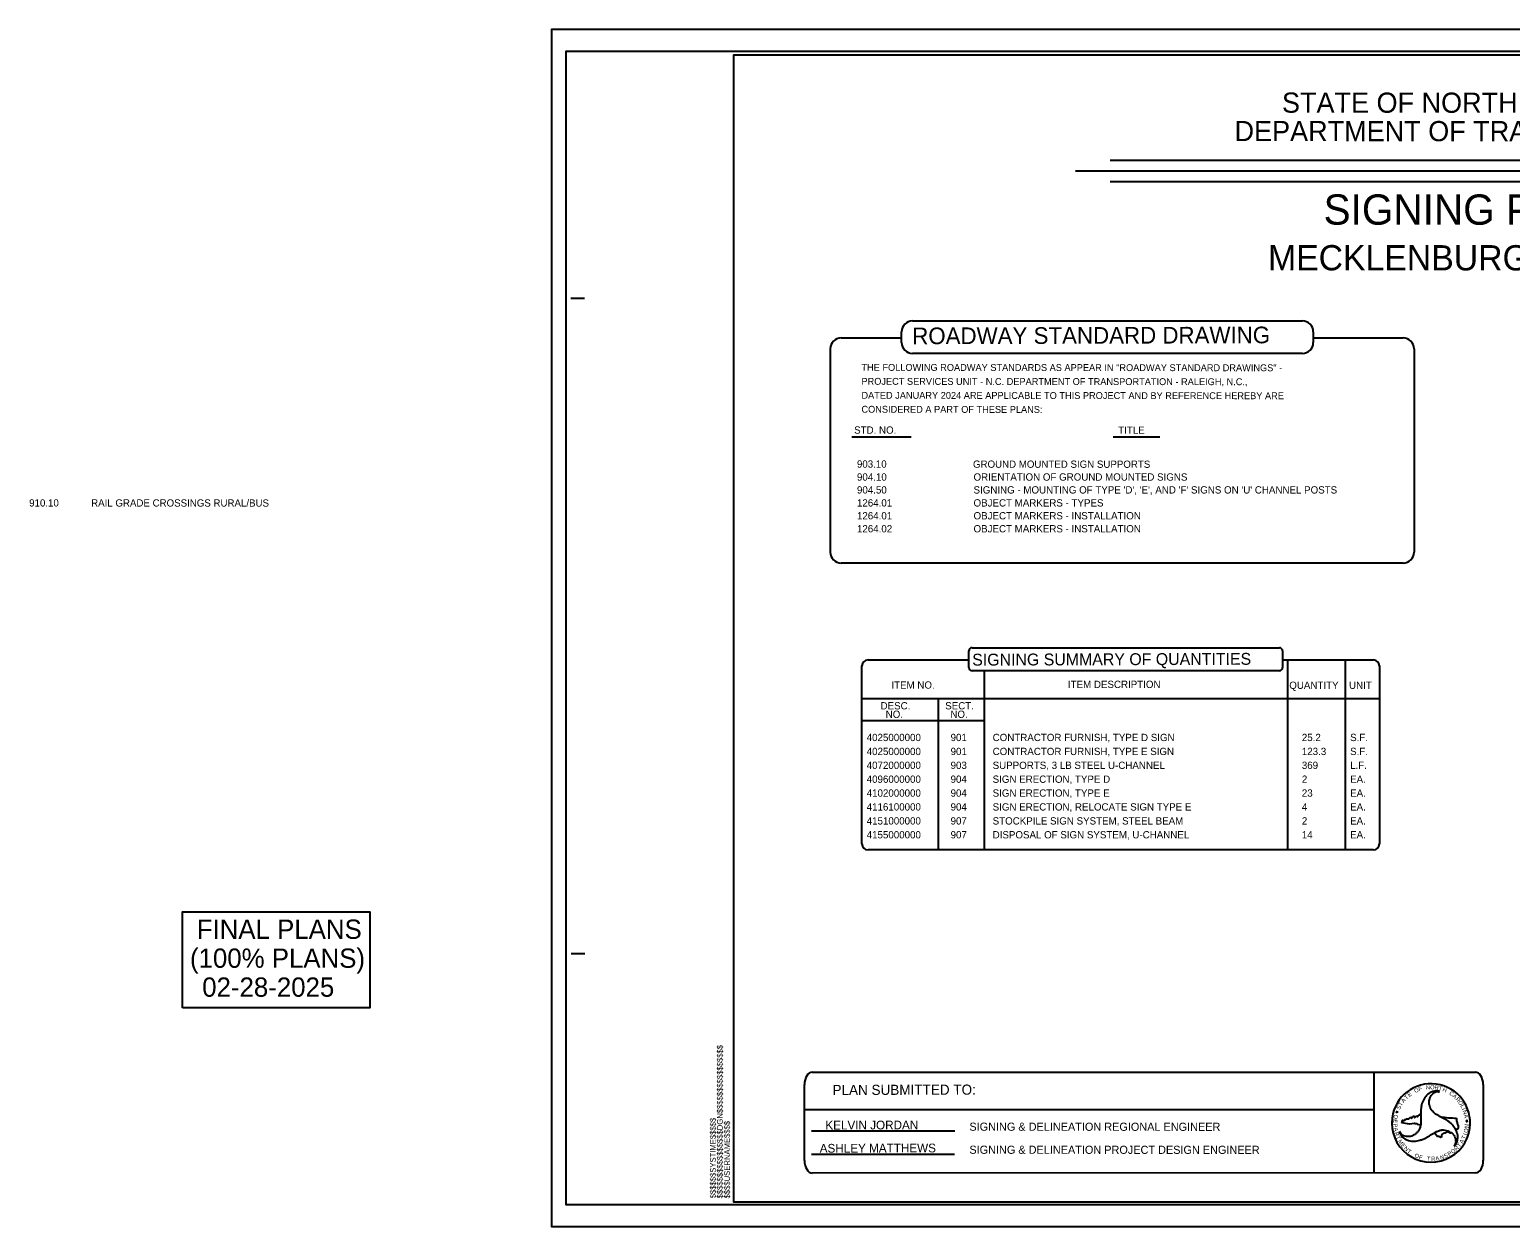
# Model space of a CAD drawing. Extents: x 2088591 to 2091186, y 751169 to 752405.
# Drawn here: x 2088591 to 2089946, y 751309 to 752405 of the extents above; entities that cross this region are included whole.
import ezdxf

# ---------------------------------------------------------------- set-up
doc = ezdxf.new("R2010")
doc.units = 0
for name, color, linetype in [('Default', 7, 'Continuous'), ('Sheet Block Title CELL', 7, 'Continuous'), ('Sheet Data Field CELL', 7, 'Continuous'), ('Sheet Plan CELL', 7, 'Continuous'), ('Sheet Sticker Incomplete CELL', 7, 'Continuous'), ('Sheet Sticker Preliminary CELL', 7, 'Continuous'), ('Sheet Title CELL', 7, 'Continuous'), ('Typical Detail Wedge1 CELL', 7, 'Continuous')]:
    doc.layers.add(name, color=color, linetype=linetype)

msp = doc.modelspace()

# ---------------------------------------------------------------- linework, layer by layer
at = {"layer": 'Default'}
for p, q in [((2089307.2, 751450), (2089914.1, 751450.1)), ((2089821.1, 751450.1), (2089821.1, 751357.8)), ((2089300, 751369.2), (2089300, 751438.6)), ((2089921.3, 751438.6), (2089921.4, 751369.3)), ((2089300, 751415.7), (2089821.1, 751415.9)), ((2089306.4, 751396.3), (2089437.6, 751396.2)), ((2089306.4, 751375.1), (2089437.5, 751375)), ((2089914.2, 751357.8), (2089307.2, 751357.7))]:
    msp.add_line(p, q, dxfattribs=at)
for centre, major_axis, start_param, end_param in [((2089307.2, 751438.6), (0, 11.5), 0.000702, 1.571498), ((2089914.1, 751438.6), (0, 11.5), 4.713091, 6.283887), ((2089307.2, 751369.2), (0, -11.5), 4.713091, 6.283887), ((2089914.2, 751369.3), (0, -11.5), 0.000702, 1.571498)]:
    msp.add_ellipse(centre, major_axis=major_axis, ratio=0.62659, start_param=start_param, end_param=end_param, dxfattribs=at)
at = {"layer": 'Sheet Block Title CELL'}
msp.add_lwpolyline([(2090751.5, 752404.7), (2089068.6, 752404.7), (2089068.6, 751308.8), (2090751.5, 751308.8)], close=True, dxfattribs=at)
at = {"layer": 'Sheet Plan CELL'}
for p, q in [((2089081.6, 751328.8), (2089081.6, 751328.8)), ((2089068.6, 751308.8), (2089068.6, 751308.8))]:
    msp.add_line(p, q, dxfattribs=at)
at = {"layer": 'Sheet Sticker Incomplete CELL'}
msp.add_lwpolyline([(2090735.1, 752381.4), (2089235.1, 752381.4), (2089235.1, 751331.4), (2090735.1, 751331.4)], close=True, dxfattribs=at)
at = {"layer": 'Sheet Sticker Preliminary CELL'}
msp.add_lwpolyline([(2088730.8, 751508.9), (2088730.8, 751597), (2088902.2, 751597), (2088902.2, 751508.9)], close=True, dxfattribs=at)
at = {"layer": 'Sheet Title CELL'}
for p, q in [((2089580, 752285.1), (2090272.1, 752285.1)), ((2089548, 752275.3), (2090302.4, 752275.3)), ((2089580, 752265.6), (2090272.1, 752265.6)), ((2089323.7, 752112.4), (2089323.7, 751926.2)), ((2089858, 752112.4), (2089858, 751926.2)), ((2089343.5, 752031.8), (2089397.7, 752031.7)), ((2089582.5, 752031.7), (2089625.2, 752031.7)), ((2089742.1, 751827.6), (2089742.1, 751653.5)), ((2089795.1, 751827.5), (2089795.1, 751653.5)), ((2089464.4, 751817.5), (2089464.4, 751653.5)), ((2089364.9, 751792.3), (2089826.3, 751792.3)), ((2089422.8, 751653.5), (2089422.8, 751792.3)), ((2089881.4, 751432.4), (2089881.3, 751432.3)), ((2089881.4, 751432.4), (2089881.3, 751432.3)), ((2089841.9, 751413.5), (2089841.5, 751414)), ((2089841.5, 751414), (2089842.1, 751413.9)), ((2089841.7, 751412.9), (2089841.9, 751413.5)), ((2089842.2, 751413.2), (2089841.7, 751412.9)), ((2089842.1, 751413.9), (2089842.4, 751414.4)), ((2089842.7, 751412.8), (2089842.2, 751413.2)), ((2089842.4, 751414.4), (2089842.5, 751413.8)), ((2089842.5, 751413.8), (2089843.2, 751413.7)), ((2089843.2, 751413.7), (2089842.6, 751413.4)), ((2089842.6, 751413.4), (2089842.7, 751412.8)), ((2089846.9, 751403.5), (2089847.3, 751405.7)), ((2089853.9, 751402.3), (2089846.9, 751403.5)), ((2089858.1, 751402.9), (2089853.9, 751402.3)), ((2089882.3, 751409.1), (2089882.3, 751409.1)), ((2089906.1, 751405.6), (2089905.5, 751405.7)), ((2089905.5, 751405.7), (2089905.9, 751405.2)), ((2089905.9, 751405.2), (2089905.7, 751404.6)), ((2089905.7, 751404.6), (2089906.2, 751404.9)), ((2089906.4, 751406.1), (2089906.1, 751405.6)), ((2089906.2, 751404.9), (2089906.7, 751404.5)), ((2089906.5, 751405.5), (2089906.4, 751406.1)), ((2089907.1, 751405.4), (2089906.5, 751405.5)), ((2089906.6, 751405.1), (2089907.1, 751405.4)), ((2089906.7, 751404.5), (2089906.6, 751405.1)), ((2089864.1, 751401.6), (2089861.2, 751402.1)), ((2089879.4, 751390.9), (2089876.7, 751394.6)), ((2089876.7, 751394.6), (2089876.7, 751394.6))]:
    msp.add_line(p, q, dxfattribs=at)
for points in [[(2089398.9, 752138), (2089755.8, 752138)], [(2089333.7, 752122.4), (2089388.9, 752122.4)], [(2089388.9, 752118.2), (2089388.9, 752128)], [(2089765.8, 752128), (2089765.8, 752118.2)], [(2089765.8, 752122.4), (2089848, 752122.4)], [(2089755.8, 752108.2), (2089398.9, 752108.2)], [(2089848, 751916.2), (2089333.7, 751916.2)], [(2089453.5, 751838.7), (2089734.7, 751838.7)], [(2089358.2, 751827.5), (2089450.5, 751827.5)], [(2089450.5, 751820.5), (2089450.5, 751835.7)], [(2089737.7, 751835.7), (2089737.7, 751820.5)], [(2089737.7, 751827.5), (2089820.8, 751827.5)], [(2089352.7, 751659), (2089352.7, 751822)], [(2089734.7, 751817.5), (2089453.5, 751817.5)], [(2089826.3, 751822), (2089826.3, 751659)], [(2089464.4, 751771.8), (2089352.7, 751771.8), (2089352.7, 751792.3), (2089422.8, 751792.3)], [(2089820.8, 751653.5), (2089358.2, 751653.5)]]:
    msp.add_lwpolyline(points, dxfattribs=at)
for centre, radius, start, end in [((2089398.9, 752128), 10, 90, 180), ((2089755.8, 752128), 10, 0, 90), ((2089333.7, 752112.4), 10, 90, 180), ((2089848, 752112.4), 10, 0, 90), ((2089398.9, 752118.2), 10, 180, 270), ((2089755.8, 752118.2), 10, 270, 0), ((2089333.7, 751926.2), 10, 180, 270), ((2089848, 751926.2), 10, 270, 0), ((2089453.5, 751835.7), 3, 90, 180), ((2089734.7, 751835.7), 3, 0, 90), ((2089358.2, 751822), 5.5, 90, 180), ((2089820.8, 751822), 5.5, 0, 90), ((2089453.5, 751820.5), 3, 180, 270), ((2089734.7, 751820.5), 3, 270, 0), ((2089358.2, 751659), 5.5, 180, 270), ((2089820.8, 751659), 5.5, 270, 0), ((2089873.5, 751403.5), 35.9, 352.4211, 172.4211), ((2089873.5, 751403.5), 35.9, 172.4211, 352.4211), ((2089904.5, 751605.2), 197.4, 258.0996, 258.1992), ((2089904.5, 751605.2), 197.4, 263.5387, 267.7447)]:
    msp.add_arc(centre, radius, start, end, dxfattribs=at)
for points in [[(2089881.3, 751432.3), (2089880.5, 751432.7), (2089878, 751432.9), (2089875.4, 751432.4), (2089875.2, 751432.3), (2089873.8, 751431.8), (2089872.4, 751431), (2089870.1, 751429.4), (2089868.2, 751427.2), (2089867.5, 751426.3), (2089866.9, 751425.1), (2089865.7, 751422.6), (2089864.9, 751420.2), (2089864.4, 751417.2), (2089864.1, 751414.6), (2089864.2, 751411.9), (2089864.3, 751409.2), (2089864.3, 751406.5), (2089864.3, 751403.8), (2089864, 751401.2), (2089863.9, 751400.9), (2089863.1, 751398.2), (2089861.6, 751395.8), (2089859.9, 751394), (2089858.9, 751393.1), (2089857.5, 751392.3), (2089856.7, 751391.8), (2089854.9, 751391.2), (2089852.3, 751391), (2089849.8, 751391.4), (2089847.7, 751392.3), (2089845.9, 751393.8), (2089844.6, 751395.8)], [(2089894.6, 751382.3), (2089895.3, 751382.8), (2089896.8, 751384.9), (2089897.7, 751387.4), (2089897.7, 751387.6), (2089897.9, 751389), (2089898, 751390.7), (2089897.7, 751393.5), (2089896.8, 751396.1), (2089896.4, 751397.3), (2089895.6, 751398.4), (2089894.1, 751400.7), (2089892.3, 751402.6), (2089890, 751404.5), (2089887.9, 751406), (2089885.5, 751407.4), (2089883.1, 751408.6), (2089880.8, 751409.9), (2089878.4, 751411.3), (2089876.3, 751412.9), (2089876.2, 751413.1), (2089874.2, 751415.2), (2089872.9, 751417.6), (2089872.1, 751420.1), (2089871.9, 751421.3), (2089871.9, 751422.9), (2089871.9, 751423.9), (2089872.3, 751425.7), (2089873.3, 751428.1), (2089875, 751430), (2089876.8, 751431.4), (2089879, 751432.2), (2089881.3, 751432.3), (2089881.4, 751432.4)], [(2089847.3, 751405.7), (2089847.2, 751405.9), (2089847.7, 751406.1), (2089848.6, 751405.6), (2089849.2, 751405.9), (2089849.3, 751406.4), (2089849.7, 751406.8), (2089850.4, 751406.6), (2089851.2, 751407.3), (2089851.8, 751407.4), (2089853.1, 751407.2), (2089854.7, 751408.5), (2089855.4, 751408.5), (2089855.5, 751408.1), (2089855.9, 751408), (2089856.7, 751409.1), (2089856.9, 751409.3), (2089858.1, 751409.6), (2089858.4, 751409.3), (2089858.4, 751408.7), (2089858.5, 751408.6), (2089858.9, 751408.8), (2089859.6, 751409.4), (2089860.6, 751409.8), (2089861.6, 751409.5), (2089862, 751410.4), (2089863.3, 751411.1), (2089863.7, 751411.5), (2089863.8, 751412.1)], [(2089861.2, 751402.1), (2089860.9, 751402.6), (2089860.4, 751402.9), (2089859.6, 751402.6), (2089859, 751402.7), (2089858.4, 751403.2), (2089858.1, 751402.9)], [(2089864.2, 751412), (2089864.2, 751411.9), (2089864.3, 751409.2), (2089864.3, 751406.5), (2089864.3, 751403.8), (2089864.1, 751401.7)], [(2089896.1, 751397.7), (2089895.6, 751398.4), (2089894.1, 751400.7), (2089892.3, 751402.6), (2089890, 751404.5), (2089887.9, 751406), (2089885.5, 751407.4), (2089883.1, 751408.6), (2089882.3, 751409.1)], [(2089896.8, 751408), (2089897, 751405.4), (2089897.9, 751402.3), (2089898.5, 751400.6), (2089898.3, 751399.2), (2089897.8, 751397.7), (2089896.1, 751397.7)], [(2089844.6, 751395.8), (2089844.8, 751394.9), (2089845.8, 751392.6), (2089847.5, 751390.6), (2089847.7, 751390.5), (2089848.8, 751389.5), (2089850.3, 751388.7), (2089852.8, 751387.5), (2089855.6, 751387), (2089856.7, 751386.8), (2089858.1, 751386.9), (2089860.8, 751387.1), (2089863.3, 751387.7), (2089866.2, 751388.7), (2089868.6, 751389.7), (2089870.9, 751391.1), (2089873.2, 751392.6), (2089875.5, 751393.9), (2089877.8, 751395.3), (2089880.3, 751396.3), (2089880.6, 751396.4), (2089883.4, 751397.1), (2089886.1, 751396.9), (2089888.6, 751396.4), (2089889.9, 751395.9), (2089891.2, 751395.1), (2089892, 751394.7), (2089893.5, 751393.5), (2089895, 751391.3), (2089895.8, 751389), (2089896.1, 751386.7), (2089895.7, 751384.4), (2089894.6, 751382.3)], [(2089876.7, 751394.6), (2089877.8, 751395.3), (2089880.3, 751396.3), (2089880.6, 751396.4), (2089883.4, 751397.1), (2089886.1, 751396.9), (2089888.6, 751396.4), (2089889.9, 751395.9), (2089891.2, 751395.1), (2089892, 751394.7)], [(2089892, 751394.7), (2089891.5, 751394.1), (2089891, 751394.1), (2089890.1, 751395.1), (2089888.9, 751395), (2089888.4, 751395.4), (2089888, 751395.4), (2089887, 751394.4), (2089885.8, 751394.3), (2089883.6, 751393.2), (2089883.1, 751392.4), (2089883, 751390.6), (2089882.5, 751390.3), (2089882, 751390.5), (2089880.8, 751391.1), (2089879.4, 751390.9)]]:
    msp.add_spline(points, degree=3, dxfattribs=at)
at = {"layer": 'Typical Detail Wedge1 CELL'}
for p, q in [((2089086.2, 752158.8), (2089098.7, 752158.8)), ((2089086.5, 751558.8), (2089099, 751558.8))]:
    msp.add_line(p, q, dxfattribs=at)
msp.add_lwpolyline([(2090747, 752384.7), (2089081.6, 752384.7), (2089081.6, 751328.8), (2090747, 751328.8)], close=True, dxfattribs=at)

# ---------------------------------------------------------------- texts
at = {"layer": 'Default'}
for s, height, rotation, p in [('ROADWAY STANDARD DRAWING', 15.257, 0.1557, (2089398.7, 752116.6)), ('THE FOLLOWING ROADWAY STANDARDS AS APPEAR IN "ROADWAY STANDARD DRAWINGS" -', 6.3, 359.9332, (2089352.2, 752092.3)), ('PROJECT SERVICES UNIT - N.C. DEPARTMENT OF TRANSPORTATION - RALEIGH, N.C.,', 6.3, 359.9332, (2089352.2, 752079.5)), ('DATED JANUARY 2024 ARE APPLICABLE TO THIS PROJECT AND BY REFERENCE HEREBY ARE ', 6.3, 359.9332, (2089352.2, 752066.7)), ('CONSIDERED A PART OF THESE PLANS:', 6.3, 359.9332, (2089352.2, 752053.9)), ('STD. NO.', 6.67, 359.9734, (2089345.5, 752034.7)), ('TITLE', 6.67, 359.9734, (2089587.2, 752034.6)), ('903.10', 6.64, 359.9734, (2089348.1, 752003.6)), ('GROUND MOUNTED SIGN SUPPORTS', 6.638, 359.9734, (2089454.3, 752003.5)), ('910.10            RAIL GRADE CROSSINGS RURAL/BUS', 6.638, 359.9734, (2088590.4, 751968)), ('SIGNING SUMMARY OF QUANTITIES', 10.875, 0.1779, (2089453.6, 751822.3)), ('ITEM NO.', 6.67, 0.0223, (2089379.6, 751801.2)), ('ITEM DESCRIPTION', 6.671, 0.0223, (2089541.2, 751801.8)), ('QUANTITY', 6.67, 0.0223, (2089743.8, 751801)), ('UNIT', 6.67, 0.0223, (2089798.5, 751801)), ('DESC.', 6.67, 0.0223, (2089369.7, 751782.2)), ('SECT.', 6.67, 0.0223, (2089428.9, 751782.2)), ('NO.', 6.67, 0.0223, (2089374.4, 751774.4)), ('NO.', 6.67, 0.0223, (2089433.6, 751774.4)), ('$$$$$$$$$$$$$$$$DGN$$$$$$$$$$$$$$$$', 5.25, 90, (2089225.2, 751334.4)), ('PLAN SUBMITTED TO:', 9.247, 0.1557, (2089325.7, 751429.1)), ('$$$$$$SYSTIME$$$$$', 5.25, 90, (2089218.9, 751334.5)), ('$$$$USERNAME$$$$', 5.25, 90, (2089231.8, 751334.4)), ('KELVIN JORDAN', 8, 0.1557, (2089319.2, 751397.5)), ('SIGNING & DELINEATION REGIONAL ENGINEER', 7.45, 359.9734, (2089451, 751396.4)), ('ASHLEY MATTHEWS', 8, 0.1557, (2089314, 751376.3)), ('SIGNING & DELINEATION PROJECT DESIGN ENGINEER', 7.45, 359.9734, (2089451, 751375.3))]:
    msp.add_text(s, height=height, rotation=rotation, dxfattribs=at).set_placement(p)
for s, height, p in [('4025000000', 6.67, (2089357, 751753.2)), ('901', 6.67, (2089433.8, 751753.2)), ('CONTRACTOR FURNISH, TYPE D SIGN', 6.671, (2089472.3, 751753.2)), ('25.2', 6.67, (2089755.3, 751753.2)), ('S.F.', 6.67, (2089799.5, 751753.2)), ('4025000000', 6.67, (2089357, 751740.4)), ('901', 6.67, (2089433.8, 751740.4)), ('CONTRACTOR FURNISH, TYPE E SIGN', 6.671, (2089472.3, 751740.4)), ('123.3', 6.67, (2089755.3, 751740.4)), ('S.F.', 6.67, (2089799.5, 751740.4)), ('4072000000', 6.67, (2089357, 751727.7)), ('903', 6.67, (2089433.8, 751727.7)), ('SUPPORTS, 3 LB STEEL U-CHANNEL', 6.671, (2089472.3, 751727.7)), ('369', 6.67, (2089755.3, 751727.7)), ('L.F.', 6.67, (2089799.5, 751727.7)), ('4096000000', 6.67, (2089357, 751715)), ('904', 6.67, (2089433.8, 751715)), ('SIGN ERECTION, TYPE D', 6.671, (2089472.3, 751715)), ('2', 6.67, (2089755.3, 751715)), ('EA.', 6.67, (2089799.5, 751715)), ('4102000000', 6.67, (2089357, 751702.3)), ('904', 6.67, (2089433.8, 751702.3)), ('SIGN ERECTION, TYPE E', 6.671, (2089472.3, 751702.3)), ('23', 6.67, (2089755.3, 751702.3)), ('EA.', 6.67, (2089799.5, 751702.3)), ('4116100000', 6.67, (2089357, 751689.6)), ('904', 6.67, (2089433.8, 751689.6)), ('SIGN ERECTION, RELOCATE SIGN TYPE E', 6.671, (2089472.3, 751689.6)), ('4', 6.67, (2089755.3, 751689.6)), ('EA.', 6.67, (2089799.5, 751689.6)), ('4151000000', 6.67, (2089357, 751676.8)), ('907', 6.67, (2089433.8, 751676.8)), ('STOCKPILE SIGN SYSTEM, STEEL BEAM', 6.671, (2089472.3, 751676.8)), ('2', 6.67, (2089755.3, 751676.8)), ('EA.', 6.67, (2089799.5, 751676.8)), ('4155000000', 6.67, (2089357, 751664.1)), ('907', 6.67, (2089433.8, 751664.1)), ('DISPOSAL OF SIGN SYSTEM, U-CHANNEL', 6.671, (2089472.3, 751664.1)), ('14', 6.67, (2089755.3, 751664.1)), ('EA.', 6.67, (2089799.5, 751664.1))]:
    msp.add_text(s, height=height, dxfattribs=at).set_placement(p)
at = {"layer": 'Sheet Data Field CELL'}
for s, height, p in [('STATE OF NORTH CAROLINA', 18.494, (2089737.1, 752328.6)), ('DEPARTMENT OF TRANSPORTATION', 18.494, (2089693.7, 752302.6)), ('SIGNING PLAN', 27.74, (2089775.2, 752226.1)), ('MECKLENBURG COUNTY', 23.116, (2089724.3, 752184.3))]:
    msp.add_text(s, height=height, rotation=359.9734, dxfattribs=at).set_placement(p)
at = {"layer": 'Sheet Sticker Preliminary CELL'}
for s, height, p in [('FINAL PLANS', 17.671, (2088743.8, 751572.1)), ('(100% PLANS)', 17.671, (2088737.6, 751545.6)), ('02-28-2025', 17.67, (2088748.8, 751519.1))]:
    msp.add_text(s, height=height, rotation=360, dxfattribs=at).set_placement(p)
at = {"layer": 'Sheet Title CELL'}
for s, height, p in [('904.10', 6.67, (2089348.1, 751991.7)), ('904.50', 6.67, (2089348.1, 751979.9)), ("SIGNING - MOUNTING OF TYPE 'D', 'E', AND 'F' SIGNS ON 'U' CHANNEL POSTS", 6.671, (2089454.8, 751979.9)), ('ORIENTATION OF GROUND MOUNTED SIGNS', 6.671, (2089454.8, 751991.7)), ('1264.01', 6.67, (2089348.1, 751968)), ('OBJECT MARKERS - TYPES', 6.671, (2089454.8, 751968)), ('1264.01', 6.67, (2089348.1, 751956.2)), ('OBJECT MARKERS - INSTALLATION', 6.671, (2089454.8, 751956.2)), ('1264.02', 6.67, (2089348.1, 751944.3)), ('OBJECT MARKERS - INSTALLATION', 6.671, (2089454.8, 751944.3))]:
    msp.add_text(s, height=height, dxfattribs=at).set_placement(p)
for s, height, rotation, p in [('E', 3.72, 36.5781, (2089853.6, 751427.2)), ('O', 3.74, 24.6387, (2089859.1, 751430.9)), ('F', 3.74, 17.4918, (2089862.7, 751432.5)), ('N', 3.73, 5.4049, (2089869, 751434.1)), ('O', 3.74, 357.9068, (2089872.7, 751434.4)), ('R', 3.73, 351.2969, (2089876.6, 751434.3)), ('T', 3.74, 344.6472, (2089880.1, 751433.8)), ('H', 3.73, 337.5625, (2089883.7, 751432.8)), ('C', 3.72, 325.2202, (2089889.8, 751429.9)), ('A', 3.73, 317.7231, (2089892.8, 751427.7)), ('S', 3.73, 64.1774, (2089845, 751415.4)), ('T', 3.74, 57.8012, (2089846.5, 751418.6)), ('A', 3.75, 50.7489, (2089848.5, 751421.7)), ('T', 3.72, 43.6937, (2089851, 751424.7)), ('R', 3.73, 311.3592, (2089895.7, 751425.1)), ('O', 3.74, 304.2396, (2089898, 751422.5)), ('L', 3.72, 298.0059, (2089900.2, 751419.2)), ('I', 3.74, 294.0166, (2089901.7, 751416.3)), ('E', 3.72, 266.562, (2089839, 751407)), ('P', 3.73, 274.0944, (2089838.9, 751402.9)), ('D', 3.73, 260.2741, (2089839.7, 751411.2)), ('N', 3.73, 288.3165, (2089902.4, 751414.6)), ('A', 3.73, 280.8845, (2089903.5, 751411.1)), ('A', 3.73, 280.687, (2089839.2, 751398.9)), ('R', 3.73, 287.7556, (2089840, 751394.6)), ('T', 3.73, 294.4062, (2089841.3, 751390.7)), ('T', 3.73, 66.5957, (2089904.6, 751388.1)), ('I', 3.74, 72.2456, (2089906.3, 751391.9)), ('O', 3.72, 77.3812, (2089907, 751394.2)), ('N', 3.73, 84.6293, (2089907.9, 751398.6)), ('M', 3.72, 301.6412, (2089843.1, 751386.9)), ('E', 3.72, 309.108, (2089845.7, 751382.9)), ('N', 3.74, 316.0795, (2089848.3, 751379.8)), ('T', 3.73, 322.9215, (2089851.3, 751376.9)), ('O', 3.73, 336.2252, (2089858, 751372.5)), ('S', 3.72, 24.2515, (2089886.3, 751371.2)), ('P', 3.73, 31.4434, (2089890, 751373)), ('O', 3.74, 38.1354, (2089893.4, 751375.1)), ('R', 3.74, 45.3245, (2089896.9, 751377.9)), ('T', 3.72, 51.4242, (2089899.8, 751380.9)), ('A', 3.74, 59.5113, (2089902.4, 751384.2)), ('F', 3.73, 343.3904, (2089862.1, 751370.7)), ('T', 3.72, 356.2997, (2089869.6, 751369)), ('R', 3.74, 3.2563, (2089873.8, 751368.8)), ('A', 3.72, 10.0094, (2089877.9, 751369.1)), ('N', 3.72, 17.041, (2089882.3, 751369.9))]:
    msp.add_text(s, height=height, rotation=rotation, dxfattribs=at).set_placement(p)

doc.saveas('drawing.dxf')
